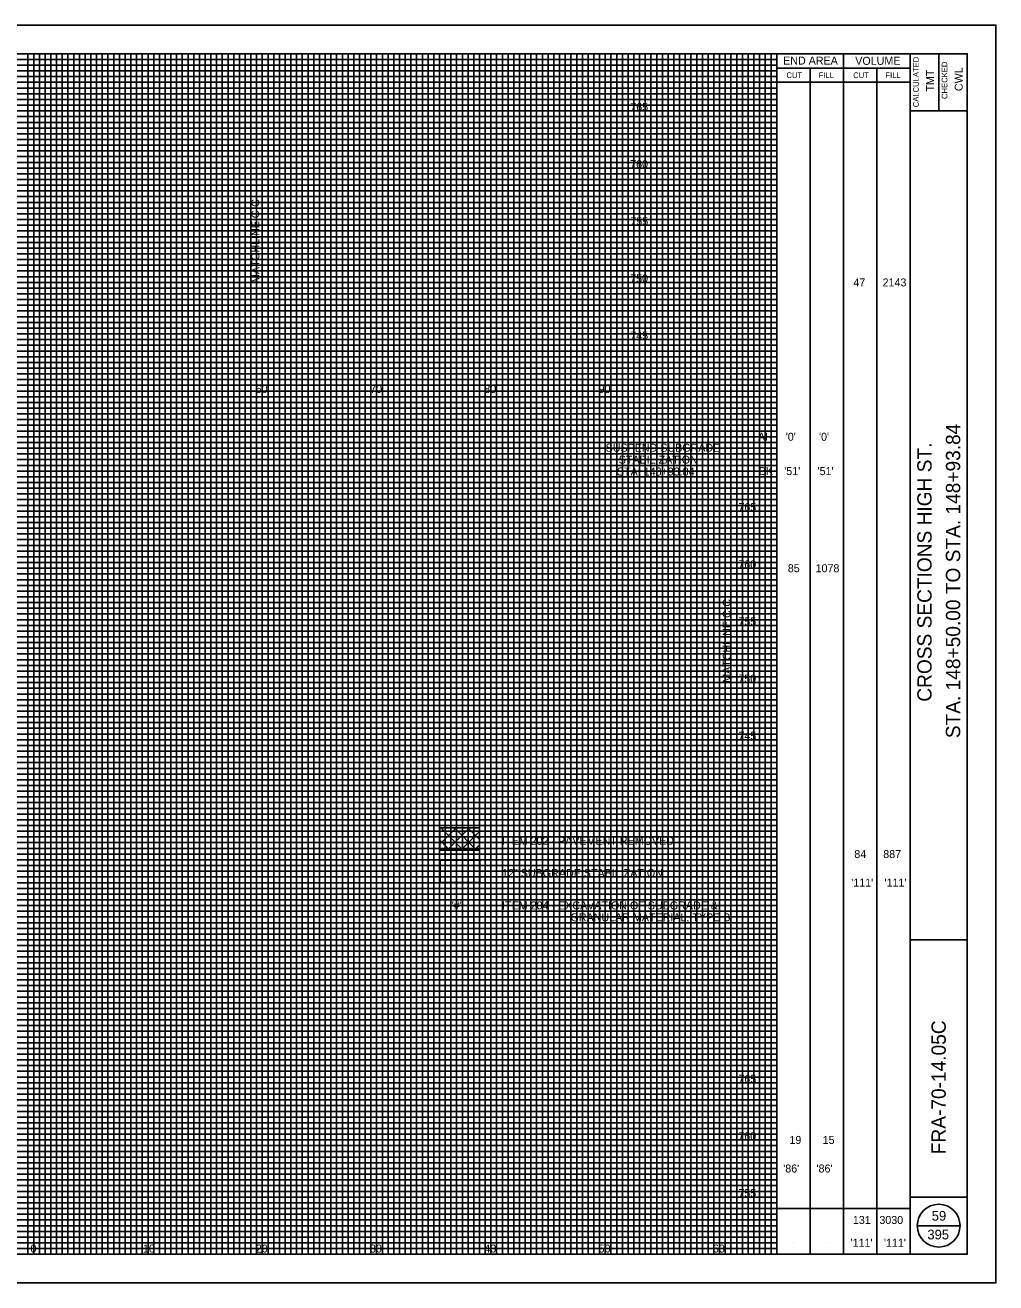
# Model space of a CAD drawing. Extents: x -10 to 160, y -2 to 568.
# Drawn here: x 75.1 to 160, y 112.5 to 222.5 of the extents above; entities that cross this region are included whole.
import ezdxf

# ---------------------------------------------------------------- set-up
doc = ezdxf.new("R2010")
doc.units = 0
for name, color, linetype in [('DR_P_Text', 7, 'Continuous'), ('SV_X_Text_Comment', 7, 'Continuous'), ('SV_X_Text_Elevation', 7, 'Continuous'), ('XS_P_Annotation', 7, 'Continuous'), ('XS_P_Finished_Grade', 7, 'Continuous'), ('XS_P_Pavt_Layers', 7, 'Continuous'), ('XS_P_Shoulder_Surface', 7, 'Continuous'), ('XS_P_Subgrade', 7, 'Continuous'), ('XS_P_Text_MarkedPoint', 7, 'Continuous')]:
    doc.layers.add(name, color=color, linetype=linetype)

msp = doc.modelspace()

# ---------------------------------------------------------------- linework, layer by layer
at = {"layer": 'SV_X_Text_Comment'}
msp.add_lwpolyline([(-10, 112.5), (160, 112.5), (160, 222.5), (-10, 222.5)], close=True, dxfattribs=at)
at = {"layer": 'SV_X_Text_Elevation'}
for p, q in [((5.83, 219.5), (140.83, 219.5)), ((5.83, 219), (140.83, 219)), ((75.33, 115), (75.33, 220)), ((76.33, 115), (76.33, 220)), ((76.83, 115), (76.83, 220)), ((77.33, 115), (77.33, 220)), ((77.83, 115), (77.83, 220)), ((78.33, 115), (78.33, 220)), ((78.83, 115), (78.83, 220)), ((79.33, 115), (79.33, 220)), ((79.83, 115), (79.83, 220)), ((80.33, 115), (80.33, 220)), ((81.33, 115), (81.33, 220)), ((81.83, 115), (81.83, 220)), ((82.33, 115), (82.33, 220)), ((82.83, 115), (82.83, 220)), ((83.33, 115), (83.33, 220)), ((83.83, 115), (83.83, 220)), ((84.33, 115), (84.33, 220)), ((84.83, 115), (84.83, 220)), ((85.33, 115), (85.33, 220)), ((86.33, 115), (86.33, 220)), ((86.83, 115), (86.83, 220)), ((87.33, 115), (87.33, 220)), ((87.83, 115), (87.83, 220)), ((88.33, 115), (88.33, 220)), ((88.83, 115), (88.83, 220)), ((89.33, 115), (89.33, 220)), ((89.83, 115), (89.83, 220)), ((90.33, 115), (90.33, 220)), ((91.33, 115), (91.33, 220)), ((91.83, 115), (91.83, 220)), ((92.33, 115), (92.33, 220)), ((92.83, 115), (92.83, 220)), ((93.33, 115), (93.33, 220)), ((93.83, 115), (93.83, 220)), ((94.33, 115), (94.33, 220)), ((94.83, 115), (94.83, 220)), ((95.33, 115), (95.33, 220)), ((96.33, 115), (96.33, 220)), ((96.83, 115), (96.83, 220)), ((97.33, 115), (97.33, 220)), ((97.83, 115), (97.83, 220)), ((98.33, 115), (98.33, 220)), ((98.83, 115), (98.83, 220)), ((99.33, 115), (99.33, 220)), ((99.83, 115), (99.83, 220)), ((100.33, 115), (100.33, 220)), ((101.33, 115), (101.33, 220)), ((101.83, 115), (101.83, 220)), ((102.33, 115), (102.33, 220)), ((102.83, 115), (102.83, 220)), ((103.33, 115), (103.33, 220)), ((103.83, 115), (103.83, 220)), ((104.33, 115), (104.33, 220)), ((104.83, 115), (104.83, 220)), ((105.33, 115), (105.33, 220)), ((106.33, 115), (106.33, 220)), ((106.83, 115), (106.83, 220)), ((107.33, 115), (107.33, 220)), ((107.83, 115), (107.83, 220)), ((108.33, 115), (108.33, 220)), ((108.83, 115), (108.83, 220)), ((109.33, 115), (109.33, 220)), ((109.83, 115), (109.83, 220)), ((110.33, 115), (110.33, 220)), ((111.33, 115), (111.33, 220)), ((111.83, 115), (111.83, 220)), ((112.33, 115), (112.33, 220)), ((112.83, 115), (112.83, 220)), ((113.33, 115), (113.33, 220)), ((113.83, 115), (113.83, 220)), ((114.33, 115), (114.33, 220)), ((114.83, 115), (114.83, 220)), ((115.33, 115), (115.33, 220)), ((116.33, 115), (116.33, 220)), ((116.83, 115), (116.83, 220)), ((117.33, 115), (117.33, 220)), ((117.83, 115), (117.83, 220)), ((118.33, 115), (118.33, 220)), ((118.83, 115), (118.83, 220)), ((119.33, 115), (119.33, 220)), ((119.83, 115), (119.83, 220)), ((120.33, 115), (120.33, 220)), ((121.33, 115), (121.33, 220)), ((121.83, 115), (121.83, 220)), ((122.33, 115), (122.33, 220)), ((122.83, 115), (122.83, 220)), ((123.33, 115), (123.33, 220)), ((123.83, 115), (123.83, 220)), ((124.33, 115), (124.33, 220)), ((124.83, 115), (124.83, 220)), ((125.33, 115), (125.33, 220)), ((126.33, 115), (126.33, 220)), ((126.83, 115), (126.83, 220)), ((127.33, 115), (127.33, 220)), ((127.83, 115), (127.83, 220)), ((128.33, 115), (128.33, 220)), ((128.83, 115), (128.83, 220)), ((129.33, 115), (129.33, 220)), ((129.83, 115), (129.83, 220)), ((130.33, 115), (130.33, 220)), ((131.33, 115), (131.33, 220)), ((131.83, 115), (131.83, 220)), ((132.33, 115), (132.33, 220)), ((132.83, 115), (132.83, 220)), ((133.33, 115), (133.33, 220)), ((133.83, 115), (133.83, 220)), ((134.33, 115), (134.33, 220)), ((134.83, 115), (134.83, 220)), ((135.33, 115), (135.33, 220)), ((136.33, 115), (136.33, 220)), ((136.83, 115), (136.83, 220)), ((137.33, 115), (137.33, 220)), ((137.83, 115), (137.83, 220)), ((138.33, 115), (138.33, 220)), ((138.83, 115), (138.83, 220)), ((139.33, 115), (139.33, 220)), ((139.83, 115), (139.83, 220)), ((140.33, 115), (140.33, 220)), ((5.83, 218.5), (140.83, 218.5)), ((5.83, 218), (140.83, 218)), ((5.83, 217.5), (140.83, 217.5)), ((5.83, 217), (140.83, 217)), ((5.83, 216.5), (140.83, 216.5)), ((5.83, 216), (140.83, 216)), ((5.83, 215.5), (140.83, 215.5)), ((5.83, 214.5), (140.83, 214.5)), ((5.83, 214), (140.83, 214)), ((5.83, 213.5), (140.83, 213.5)), ((5.83, 213), (140.83, 213)), ((5.83, 212.5), (140.83, 212.5)), ((5.83, 212), (140.83, 212)), ((5.83, 211.5), (140.83, 211.5)), ((5.83, 211), (140.83, 211)), ((5.83, 210.5), (140.83, 210.5)), ((5.83, 209.5), (140.83, 209.5)), ((5.83, 209), (140.83, 209)), ((5.83, 208.5), (140.83, 208.5)), ((5.83, 208), (140.83, 208)), ((5.83, 207.5), (140.83, 207.5)), ((5.83, 207), (140.83, 207)), ((5.83, 206.5), (140.83, 206.5)), ((5.83, 206), (140.83, 206)), ((5.83, 205.5), (140.83, 205.5)), ((5.83, 204.5), (140.83, 204.5)), ((5.83, 204), (140.83, 204)), ((5.83, 203.5), (140.83, 203.5)), ((5.83, 203), (140.83, 203)), ((5.83, 202.5), (140.83, 202.5)), ((5.83, 202), (140.83, 202)), ((5.83, 201.5), (140.83, 201.5)), ((5.83, 201), (140.83, 201)), ((5.83, 200.5), (140.83, 200.5)), ((5.83, 199.5), (140.83, 199.5)), ((5.83, 199), (140.83, 199)), ((5.83, 198.5), (140.83, 198.5)), ((5.83, 198), (140.83, 198)), ((5.83, 197.5), (140.83, 197.5)), ((5.83, 197), (140.83, 197)), ((5.83, 196.5), (140.83, 196.5)), ((5.83, 196), (140.83, 196)), ((5.83, 195.5), (140.83, 195.5)), ((5.83, 194.5), (140.83, 194.5)), ((5.83, 194), (140.83, 194)), ((5.83, 193.5), (140.83, 193.5)), ((5.83, 193), (140.83, 193)), ((5.83, 192.5), (140.83, 192.5)), ((5.83, 192), (140.83, 192)), ((5.83, 191.5), (140.83, 191.5)), ((5.83, 191), (140.83, 191)), ((5.83, 190.5), (140.83, 190.5)), ((5.83, 189.5), (140.83, 189.5)), ((5.83, 189), (140.83, 189)), ((5.83, 188.5), (140.83, 188.5)), ((5.83, 188), (140.83, 188)), ((5.83, 187.5), (140.83, 187.5)), ((5.83, 187), (140.83, 187)), ((5.83, 186.5), (140.83, 186.5)), ((5.83, 186), (140.83, 186)), ((5.83, 185.5), (140.83, 185.5)), ((5.83, 184.5), (140.83, 184.5)), ((5.83, 184), (140.83, 184)), ((5.83, 183.5), (140.83, 183.5)), ((5.83, 183), (140.83, 183)), ((5.83, 182.5), (140.83, 182.5)), ((5.83, 182), (140.83, 182)), ((5.83, 181.5), (140.83, 181.5)), ((5.83, 181), (140.83, 181)), ((5.83, 180.5), (140.83, 180.5)), ((5.83, 179.5), (140.83, 179.5)), ((5.83, 179), (140.83, 179)), ((5.83, 178.5), (140.83, 178.5)), ((5.83, 178), (140.83, 178)), ((5.83, 177.5), (140.83, 177.5)), ((5.83, 177), (140.83, 177)), ((5.83, 176.5), (140.83, 176.5)), ((5.83, 176), (140.83, 176)), ((5.83, 175.5), (140.83, 175.5)), ((5.83, 174.5), (140.83, 174.5)), ((5.83, 174), (140.83, 174)), ((5.83, 173.5), (140.83, 173.5)), ((5.83, 173), (140.83, 173)), ((5.83, 172.5), (140.83, 172.5)), ((5.83, 172), (140.83, 172)), ((5.83, 171.5), (140.83, 171.5)), ((5.83, 171), (140.83, 171)), ((5.83, 170.5), (140.83, 170.5)), ((5.83, 169.5), (140.83, 169.5)), ((5.83, 169), (140.83, 169)), ((5.83, 168.5), (140.83, 168.5)), ((5.83, 168), (140.83, 168)), ((5.83, 167.5), (140.83, 167.5)), ((5.83, 167), (140.83, 167)), ((5.83, 166.5), (140.83, 166.5)), ((5.83, 166), (140.83, 166)), ((5.83, 165.5), (140.83, 165.5)), ((5.83, 164.5), (140.83, 164.5)), ((5.83, 164), (140.83, 164)), ((5.83, 163.5), (140.83, 163.5)), ((5.83, 163), (140.83, 163)), ((5.83, 162.5), (140.83, 162.5)), ((5.83, 162), (140.83, 162)), ((5.83, 161.5), (140.83, 161.5)), ((5.83, 161), (140.83, 161)), ((5.83, 160.5), (140.83, 160.5)), ((5.83, 159.5), (140.83, 159.5)), ((5.83, 159), (140.83, 159)), ((5.83, 158.5), (140.83, 158.5)), ((5.83, 158), (140.83, 158)), ((5.83, 157.5), (140.83, 157.5)), ((5.83, 157), (140.83, 157)), ((5.83, 156.5), (140.83, 156.5)), ((5.83, 156), (140.83, 156)), ((5.83, 155.5), (140.83, 155.5)), ((5.83, 154.5), (140.83, 154.5)), ((5.83, 154), (140.83, 154)), ((5.83, 153.5), (140.83, 153.5)), ((5.83, 153), (140.83, 153)), ((5.83, 152.5), (140.83, 152.5)), ((5.83, 152), (140.83, 152)), ((5.83, 151.5), (140.83, 151.5)), ((5.83, 151), (140.83, 151)), ((5.83, 150.5), (140.83, 150.5)), ((5.83, 149.5), (140.83, 149.5)), ((5.83, 149), (140.83, 149)), ((5.83, 148.5), (140.83, 148.5)), ((5.83, 148), (140.83, 148)), ((5.83, 147.5), (140.83, 147.5)), ((5.83, 147), (140.83, 147)), ((5.83, 146.5), (140.83, 146.5)), ((5.83, 146), (140.83, 146)), ((5.83, 145.5), (140.83, 145.5)), ((5.83, 144.5), (140.83, 144.5)), ((5.83, 144), (140.83, 144)), ((5.83, 143.5), (140.83, 143.5)), ((5.83, 143), (140.83, 143)), ((5.83, 142.5), (140.83, 142.5)), ((5.83, 142), (140.83, 142)), ((5.83, 141.5), (140.83, 141.5)), ((5.83, 141), (140.83, 141)), ((5.83, 140.5), (140.83, 140.5)), ((5.83, 139.5), (140.83, 139.5)), ((5.83, 139), (140.83, 139)), ((5.83, 138.5), (140.83, 138.5)), ((5.83, 138), (140.83, 138)), ((5.83, 137.5), (140.83, 137.5)), ((5.83, 137), (140.83, 137)), ((5.83, 136.5), (140.83, 136.5)), ((5.83, 136), (140.83, 136)), ((5.83, 135.5), (140.83, 135.5)), ((5.83, 134.5), (140.83, 134.5)), ((5.83, 134), (140.83, 134)), ((5.83, 133.5), (140.83, 133.5)), ((5.83, 133), (140.83, 133)), ((5.83, 132.5), (140.83, 132.5)), ((5.83, 132), (140.83, 132)), ((5.83, 131.5), (140.83, 131.5)), ((5.83, 131), (140.83, 131)), ((5.83, 130.5), (140.83, 130.5)), ((5.83, 129.5), (140.83, 129.5)), ((5.83, 129), (140.83, 129)), ((5.83, 128.5), (140.83, 128.5)), ((5.83, 128), (140.83, 128)), ((5.83, 127.5), (140.83, 127.5)), ((5.83, 127), (140.83, 127)), ((5.83, 126.5), (140.83, 126.5)), ((5.83, 126), (140.83, 126)), ((5.83, 125.5), (140.83, 125.5)), ((5.83, 124.5), (140.83, 124.5)), ((5.83, 124), (140.83, 124)), ((5.83, 123.5), (140.83, 123.5)), ((5.83, 123), (140.83, 123)), ((5.83, 122.5), (140.83, 122.5)), ((5.83, 122), (140.83, 122)), ((5.83, 121.5), (140.83, 121.5)), ((5.83, 121), (140.83, 121)), ((5.83, 120.5), (140.83, 120.5)), ((5.83, 119.5), (140.83, 119.5)), ((5.83, 119), (140.83, 119)), ((5.83, 118.5), (140.83, 118.5)), ((5.83, 118), (140.83, 118)), ((5.83, 117.5), (140.83, 117.5)), ((5.83, 117), (140.83, 117)), ((5.83, 116.5), (140.83, 116.5)), ((5.83, 116), (140.83, 116)), ((5.83, 115.5), (140.83, 115.5))]:
    msp.add_line(p, q, dxfattribs=at)
at = {"layer": 'XS_P_Annotation'}
for p, q in [((152.5, 115), (152.5, 220)), ((155, 220), (155, 215)), ((152.5, 215), (157.5, 215)), ((152.5, 142.5), (157.5, 142.5)), ((152.5, 120), (157.5, 120))]:
    msp.add_line(p, q, dxfattribs=at)
msp.add_lwpolyline([(0, 220), (157.5, 220), (157.5, 115), (0, 115)], close=True, dxfattribs=at)
at = {"layer": 'XS_P_Finished_Grade'}
for p, q in [((140.83, 115), (140.83, 220)), ((146.67, 115), (146.67, 220)), ((140.83, 218.75), (152.5, 218.75)), ((143.75, 115), (143.75, 218.75)), ((149.58, 115), (149.58, 218.75)), ((140.83, 217.5), (152.5, 217.5)), ((140.83, 119), (152.5, 119)), ((153.12, 117.5), (156.88, 117.5)), ((142.29, 116), (142.29, 116)), ((145.21, 116), (145.21, 116)), ((148.12, 116), (148.12, 116)), ((151.04, 116), (151.04, 116))]:
    msp.add_line(p, q, dxfattribs=at)
msp.add_circle((155, 117.5), 1.87, dxfattribs=at)
at = {"layer": 'XS_P_Pavt_Layers'}
for p, q in [((111.36, 150.88), (112.78, 152.3)), ((111.45, 152.3), (113.39, 150.35)), ((112.01, 150.35), (113.96, 152.3)), ((112.63, 152.3), (114.57, 150.35)), ((113.19, 150.35), (114.83, 151.99)), ((113.81, 152.3), (114.83, 151.28)), ((111.36, 151.21), (112.22, 150.35)), ((114.37, 150.35), (114.83, 150.81))]:
    msp.add_line(p, q, dxfattribs=at)
at = {"layer": 'XS_P_Shoulder_Surface'}
msp.add_lwpolyline([(111.39, 147.52), (114.86, 147.52), (114.86, 149.47), (111.39, 149.47), (111.39, 147.52)], dxfattribs=at)
at = {"layer": 'XS_P_Subgrade'}
for p, q in [((95.83, 193.46), (95.83, 216.56)), ((135.83, 158.5), (135.83, 181.59))]:
    msp.add_line(p, q, dxfattribs=at)
for points in [[(111.36, 152.3), (114.83, 152.3), (114.83, 150.35), (111.36, 150.35)], [(111.39, 149.47), (114.86, 149.47), (114.86, 147.52), (111.39, 147.52)]]:
    msp.add_lwpolyline(points, close=True, dxfattribs=at)
at = {"layer": 'XS_P_Text_MarkedPoint'}
for p, q in [((75.83, 115), (75.83, 220)), ((80.83, 115), (80.83, 220)), ((85.83, 115), (85.83, 220)), ((90.83, 115), (90.83, 220)), ((95.83, 115), (95.83, 220)), ((100.83, 115), (100.83, 220)), ((105.83, 115), (105.83, 220)), ((110.83, 115), (110.83, 220)), ((115.83, 115), (115.83, 220)), ((120.83, 115), (120.83, 220)), ((125.83, 115), (125.83, 220)), ((130.83, 115), (130.83, 220)), ((135.83, 115), (135.83, 220)), ((5.83, 215), (140.83, 215)), ((5.83, 210), (140.83, 210)), ((5.83, 205), (140.83, 205)), ((5.83, 200), (140.83, 200)), ((5.83, 195), (140.83, 195)), ((5.83, 190), (140.83, 190)), ((5.83, 185), (140.83, 185)), ((5.83, 180), (140.83, 180)), ((5.83, 175), (140.83, 175)), ((5.83, 170), (140.83, 170)), ((5.83, 165), (140.83, 165)), ((5.83, 160), (140.83, 160)), ((5.83, 155), (140.83, 155)), ((5.83, 150), (140.83, 150)), ((5.83, 145), (140.83, 145)), ((5.83, 140), (140.83, 140)), ((5.83, 135), (140.83, 135)), ((5.83, 130), (140.83, 130)), ((5.83, 125), (140.83, 125)), ((5.83, 120), (140.83, 120))]:
    msp.add_line(p, q, dxfattribs=at)

# ---------------------------------------------------------------- texts
at = {"layer": 'DR_P_Text'}
for s, p in [('765', (128.02, 215)), ('760', (128.01, 210)), ('755', (128.03, 205)), ('750', (128.01, 200)), ('47', (147.54, 199.65)), ('2143', (150.09, 199.65)), ('745', (128.02, 195)), ('60', (95.25, 190.33)), ('70', (105.26, 190.33)), ('80', (115.25, 190.33)), ('90', (125.25, 190.33)), ('AH', (139.19, 186.15)), ("'0'", (141.62, 186.15)), ("'0'", (144.53, 186.15)), ('BK', (139.26, 183.15)), ("'51'", (141.49, 183.15)), ("'51'", (144.4, 183.15)), ('765', (137.48, 180)), ('760', (137.47, 175)), ('85', (141.8, 174.65)), ('1078', (144.23, 174.65)), ('755', (137.48, 170)), ('750', (137.47, 165)), ('745', (137.48, 160)), ('84', (147.62, 149.65)), ('887', (150.15, 149.65)), ("'111'", (147.35, 147.15)), ("'111'", (150.26, 147.15)), ("'#'", (112.4, 145.16)), ('765', (137.48, 130)), ('760', (137.47, 125)), ('19', (141.94, 124.65)), ('15', (144.85, 124.65)), ("'86'", (141.4, 122.15)), ("'86'", (144.31, 122.15)), ('755', (137.48, 120)), ('131', (147.49, 117.65)), ('3030', (149.81, 117.65)), ('0', (75.55, 115.15)), ('0', (75.55, 115.15)), ('10', (85.39, 115.15)), ('20', (95.26, 115.15)), ('30', (105.25, 115.15)), ('40', (115.25, 115.15)), ('50', (125.25, 115.15)), ('60', (135.25, 115.15)), ("'111'", (147.29, 115.65)), ("'111'", (150.21, 115.65))]:
    msp.add_text(s, height=0.7, dxfattribs=at).set_placement(p)
at = {"layer": 'XS_P_Finished_Grade'}
for s, height, p in [('END AREA', 0.7, (141.39, 219.05)), ('VOLUME', 0.7, (147.7, 219.03)), ('CUT', 0.5, (141.68, 217.87)), ('FILL', 0.5, (144.5, 217.87)), ('CUT', 0.5, (147.52, 217.87)), ('FILL', 0.5, (150.34, 217.87)), ('59', 0.85, (154.39, 117.94)), ('395', 0.85, (154.01, 116.3))]:
    msp.add_text(s, height=height, dxfattribs=at).set_placement(p)
for s, height, p in [('CALCULATED', 0.5, (153.26, 215.32)), ('CHECKED', 0.5, (155.76, 216.04)), ('TMT', 0.7, (154.6, 216.69)), ('CWL', 0.7, (157.1, 216.73)), ('STA. 148+50.00 TO STA. 148+93.84', 1.25, (156.88, 160.14)), ('CROSS SECTIONS HIGH ST.', 1.25, (154.38, 163.33)), ('FRA-70-14.05C', 1.25, (155.62, 123.75))]:
    msp.add_text(s, height=height, rotation=90, dxfattribs=at).set_placement(p)
at = {"layer": 'XS_P_Subgrade'}
for p in [(95.57, 199.95), (136.81, 164.98)]:
    msp.add_text('MATCHLINE C-C', height=0.7, rotation=90, dxfattribs=at).set_placement(p)
for s, p in [('SUSPEND SUBGRADE', (125.86, 185.19)), ('STABILIZATION', (127.01, 184.15)), ('STA. 148+93.84', (126.85, 183.11)), ('ITEM 202 - PAVEMENT REMOVED', (116.81, 150.81)), ('12" SUBGRADE STABILIZATION', (116.81, 147.99)), ('ITEM 204 - EXCAVATION OF SUBGRADE &', (116.81, 145.16)), ('GRANULAR MATERIAL, TYPE B', (122.79, 144.12))]:
    msp.add_text(s, height=0.7, dxfattribs=at).set_placement(p)

doc.saveas('drawing.dxf')
